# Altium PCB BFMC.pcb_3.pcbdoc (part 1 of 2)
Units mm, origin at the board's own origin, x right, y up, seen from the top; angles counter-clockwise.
Board outline 133.24 x 103.12 mm, 2 copper layers (Top Layer, Bottom Layer); 130 components, 62 nets, 361 pads, 103 vias.
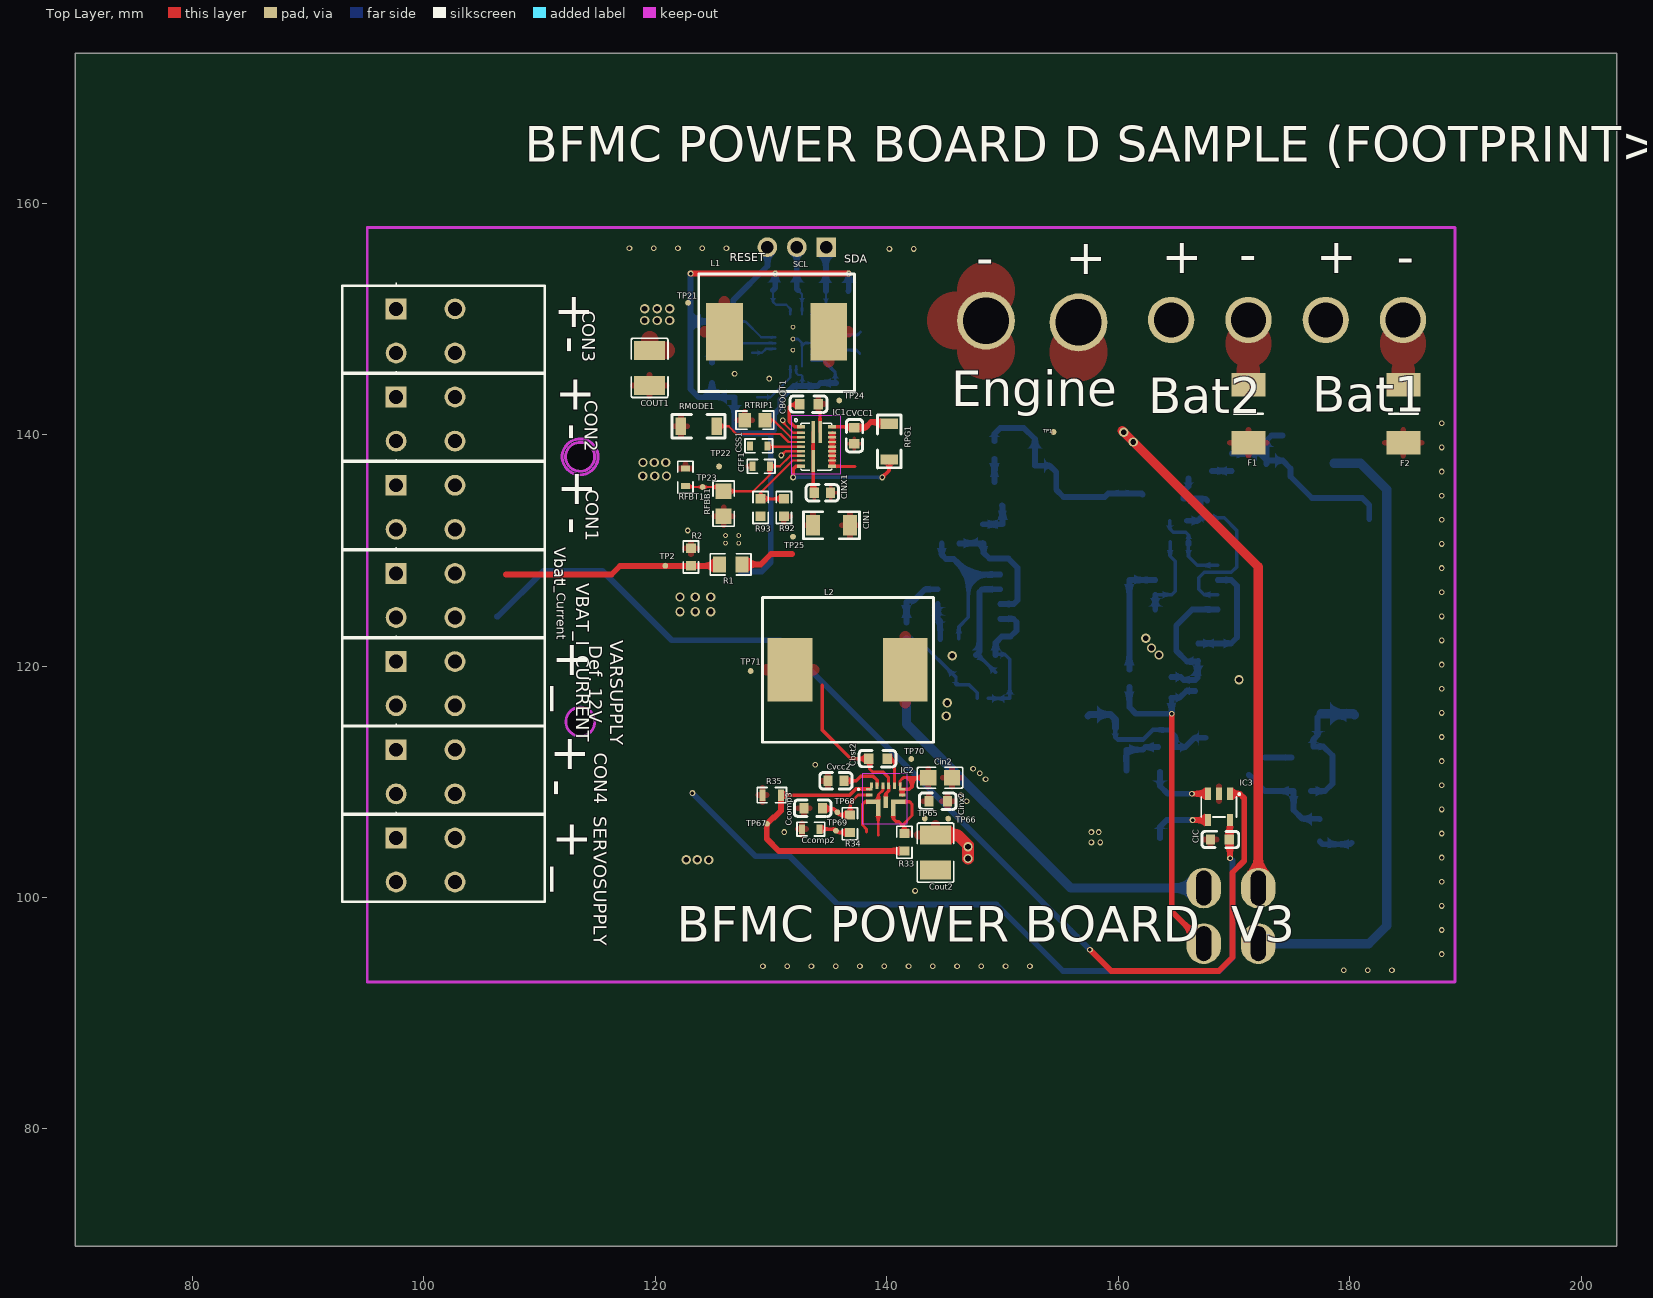
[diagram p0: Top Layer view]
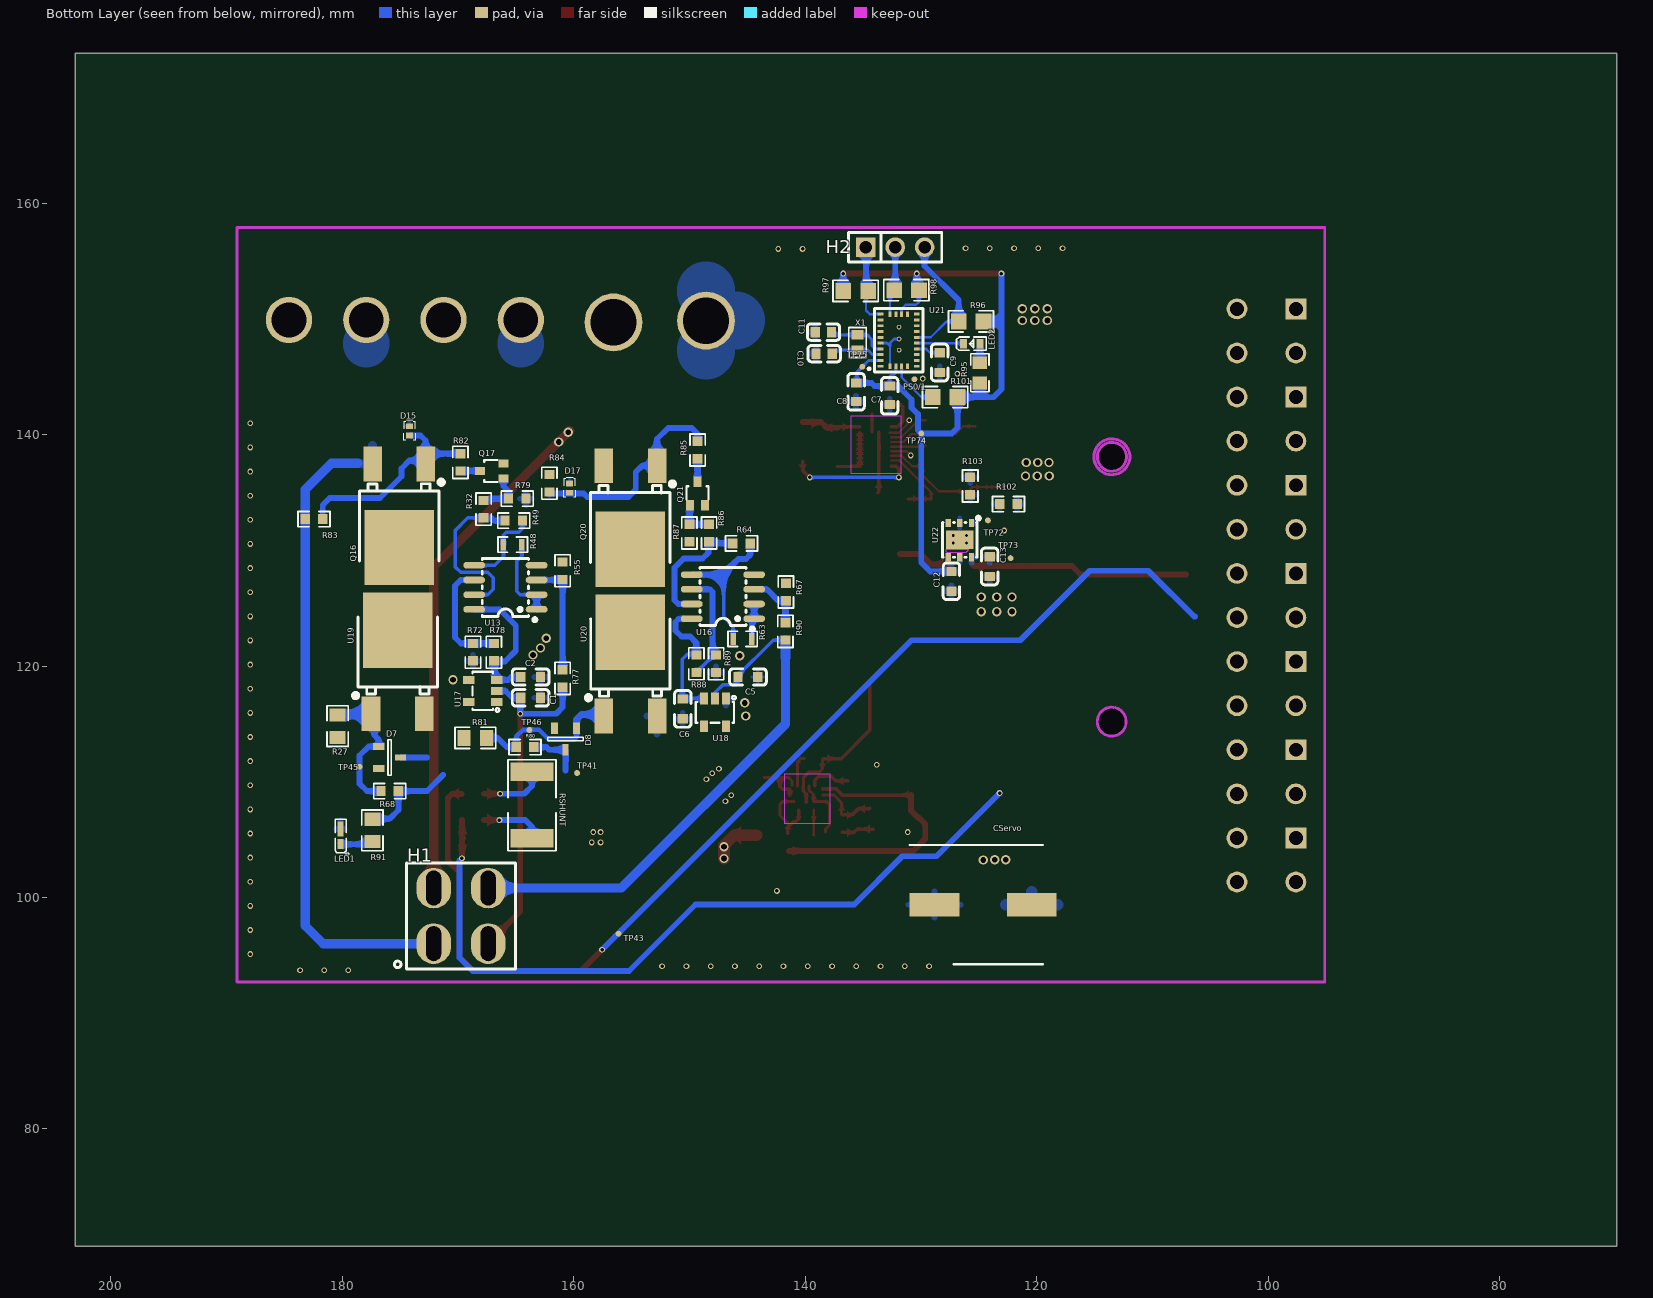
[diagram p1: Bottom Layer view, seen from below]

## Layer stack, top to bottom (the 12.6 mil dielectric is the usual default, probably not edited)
Top Layer: signal copper (thickness not stored)
Dielectric: dielectric 0.32, FR-4, Dk 4.8
Bottom Layer: signal copper (thickness not stored)

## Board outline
203.09,69.85 69.85,69.85 69.85,172.973 203.09,172.973
cut-out: 114.745,138.083 ccw(c113.495,138.083) 112.245,138.083 ccw(c113.495,138.083)
cut-out: 114.762,115.196 ccw(c113.512,115.196) 112.262,115.196 ccw(c113.512,115.196)

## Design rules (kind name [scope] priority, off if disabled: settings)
Clearance copperThickness1oz [All] p1: gap=0.178 ignorepadtopadclearanceinfootprint=FALSE except(0.102: Track-Track; 0.152: Track-SMDPad SMDPad-SMDPad Track-THPad SMDPad-THPad THPad-THPad Track-Via SMDPad-Via THPad-Via Via-Via Track-Fill SMDPad-Fill THPad-Fill Via-Fill Fill-Fill SMDPad-Region THPad-Region Via-Region Fill-Region Region-Region Track-Poly SMDPad-Poly THPad-Poly Via-Poly Fill-Poly Poly-Poly Track-Text SMDPad-Text THPad-Text Via-Text Fill-Text Region-Text Poly-Text Text-Text Track-Hole SMDPad-Hole THPad-Hole Via-Hole Fill-Hole Region-Hole Poly-Hole Text-Hole; 0.3: Track-Region Region-Poly Track-Sheet SMDPad-Sheet THPad-Sheet Via-Sheet Fill-Sheet Region-Sheet Poly-Sheet Text-Sheet Sheet-Hole)
Clearance copperThickness2oz [All] p1: gap=0.178 ignorepadtopadclearanceinfootprint=FALSE except(0.152: Track-SMDPad SMDPad-SMDPad Track-THPad SMDPad-THPad THPad-THPad Track-Via SMDPad-Via THPad-Via Via-Via Track-Fill SMDPad-Fill THPad-Fill Via-Fill Fill-Fill SMDPad-Region THPad-Region Via-Region Fill-Region Region-Region Track-Poly SMDPad-Poly THPad-Poly Via-Poly Fill-Poly Poly-Poly Track-Text SMDPad-Text THPad-Text Via-Text Fill-Text Region-Text Poly-Text Text-Text Track-Hole SMDPad-Hole THPad-Hole Via-Hole Fill-Hole Region-Hole Poly-Hole Text-Hole; 0.203: Track-Track; 0.3: Track-Region Region-Poly Track-Sheet SMDPad-Sheet THPad-Sheet Via-Sheet Fill-Sheet Region-Sheet Poly-Sheet Text-Sheet Sheet-Hole)
Clearance Supply-GND [All] p1: gap=0.178 ignorepadtopadclearanceinfootprint=FALSE except(0.5: Track-Track Track-SMDPad SMDPad-SMDPad Track-THPad SMDPad-THPad THPad-THPad Track-Via SMDPad-Via THPad-Via Via-Via Track-Fill SMDPad-Fill THPad-Fill Via-Fill Fill-Fill Track-Region SMDPad-Region THPad-Region Via-Region Fill-Region Region-Region Track-Poly SMDPad-Poly THPad-Poly Via-Poly Fill-Poly Region-Poly Poly-Poly Track-Text SMDPad-Text THPad-Text Via-Text Fill-Text Region-Text Poly-Text Text-Text Track-Sheet SMDPad-Sheet THPad-Sheet Via-Sheet Fill-Sheet Region-Sheet Poly-Sheet Text-Sheet Track-Hole SMDPad-Hole THPad-Hole Via-Hole Fill-Hole Region-Hole Poly-Hole Text-Hole Sheet-Hole)
DiffPairsRouting differentialPair [All] p1: maxuncoupledlength=10 maxlimit=5.9843 mostfreqgap=5.9843 toplayer_minwidth=5 toplayer_prefwidth=10 toplayer_maxwidth=100 bottomlayer_minwidth=5 bottomlayer_prefwidth=10 bottomlayer_maxwidth=100
PasteMaskExpansion pasteMaskExpansion [All] p1:
PlaneConnect innerPlane [All] p1: planeconnectstyle=Relief reliefexpansion=0.508 reliefentries=4 reliefconductorwidth=0.254 reliefairgap=0.254
PolygonConnect copperRegion [All] p1: connectstyle=Direct reliefentries=4 reliefconductorwidth=10 polygonreliefangle="90 Angle" airgapwidth=10
PolygonConnect copperRegion1 [All] p1: connectstyle=Relief reliefentries=4 reliefconductorwidth=10 polygonreliefangle="90 Angle" airgapwidth=10
PolygonConnect copperRegion2 [All] p1: connectstyle=Relief reliefentries=4 reliefconductorwidth=10 polygonreliefangle="90 Angle" airgapwidth=10
RoutingVias viaSize [All] p1: viastyle="Through Hole" holewidth=12.0078 minholewidth=11.811 maxholewidth=248.0314 width=24.0158 minwidth=19.685 maxwidth=393.7008
SolderMaskExpansion solderMaskExpansion [All] p1: useseparateexpansions=TRUE expansion=2.0079 expansionbottom=2.0079
Width copperThickness1oz [All] p1: maxlimit=100 minlimit=5 preferedwidth=10
Width copperThickness2oz [All] p1: maxlimit=100 minlimit=8 preferedwidth=10

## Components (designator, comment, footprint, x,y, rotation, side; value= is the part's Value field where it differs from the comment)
C1 "CAP_0201" C9 163.776,117.255 r180 bottom
C2 "CAP_0201" C9 163.776,119.055 r180 bottom
C5 "CAP_0201" C9 144.996,119.055 r180 bottom
C6 "CAP_0201" C9 150.576,116.355 r270 bottom
C7 "CAP_0201" Cbst2 132.696,143.295 r90 bottom
C8 "CAP_0201" Cbst2 135.6,143.76 r270 bottom
C9 "CAP_0201" C9 128.376,146.175 r90 bottom
C10 "CAP_0201" C0603 138.36,147 r0 bottom
C11 "CAP_0201" C0603 138.42,148.86 r0 bottom
C12 "CAP_0201" C9 127.356,127.275 r90 bottom
C13 "CAP_0201" C9 124.056,128.549 r90 bottom
CBOOT1 "EMK105 B7104KVHF" Cbst2 133.176,142.635 r0 top
Cbst2 "CAP_0201" Cbst2 139.139,112.005 r0 top
Ccomp2 "CAP_0201" "0603 0.5x0.8" 133.424,105.909 r0 top
Ccomp3 "CAP_0201" Cbst2 133.536,107.715 r0 top
CFF1 "C1005C0G1H220J" "0603 0.5x0.8" 129.138,137.264 r0 top
CIC "C2012X7S1C106K" Cbst2 168.876,105.015 r180 top
CIN1 "GCJ31CC71E106K" "Cin1 Aditome" 135.322,132.167 r0 top
Cin2 "CAP_0201" c0805 144.6,110.354 r180 top
CINX1 "GCM188C71A225K" C0603 134.433,134.961 r0 top
Cinx2 "CAP_0201" Cbst2 144.346,108.322 r0 top
CON1 "switch" "new connector" 100.14,133.721 r270 top
CON2 "switch" "new connector" 100.14,141.341 r270 top
CON3 "switch" "new connector" 100.14,148.961 r270 top
CON4 "switch" "new connector" 100.14,110.861 r270 top
COUT1 "EMK325ABJ107MM-T" C1210 119.5,145.76 r270 top
Cout2 "CAP_0201" C1210 144.207,103.879 r90 top
CServo "GCM188C71A225K" CAPAE1030X1050N 124.613,99.382 r180 bottom
CSS1 "C1608X7R1H154K" "0603 0.5x0.8" 128.933,139.017 r180 top
CVCC1 "GCM188C71A225K" C0603 137.2,139.9 r270 top
Cvcc2 "CAP_0201" C0603 135.607,110.079 r0 top
D7 "SZBZX84C18ET1G" SZBZX84C18ET1G 175.9,112.1 r270 bottom
D8 "SZBZX84C18ET1G" SZBZX84C18ET1G 160.7,113.7 r0 bottom
D15 "PZU6.8B2L,315" DFN1006-2L-RD 174.189,140.325 r270 bottom
D17 "PZU6.8B2L,315" DFN1006-2L-RD 160.346,135.372 r270 bottom
F1 "0451015.MRL" FUSC6127X294N 171.24,141.796 r270 top
F2 "0451015.MRL" FUSC6127X294N 184.628,141.796 r270 top
H1 "switch" M2021BB1W01 169.744,98.415 r0 bottom
H2 "HDR-M_2.54_1x3P" HDR-TH_3P-P2.54-V-M 132.216,156.195 r180 bottom
IC1 "TPS548A28RWWR" TPS548B28RWWR 133.925,138.963 r0 top
IC2 "TPS61288RQQR" TPS61288RQQR 139.907,108.479 r0 top
IC3 "INA180A2QDBVRQ1" ina180a2qdbvrq1 168.696,107.835 r180 top
L1 "IHLP4040DZERR47M11" IHLP4040DZERR47M11 130.476,148.815 r0 top
L2 "L_0402" "DR127-3R3-R (L2)" 136.607,119.692 r0 top
LED1 "19-213/Y2C-CQ2R2L/3T(CY)" LEDGREEN 180.156,105.375 r90 bottom
LED2 "TLMS1100-GS08" "LED2 RED" 125.676,147.855 r180 bottom
PS0/1 "Test-Point" Test-Point-0.5mm 130.56,144.78 r180 bottom
Q16 "IPD50P04P4-13" pg-to252-3_l6.3-w6.5-p4.57-ls10.0-br-cw 175.078,133.848 r90 bottom
Q17 "BC846W" SOT-323-3_L2.2-W1.3-P1.30-LS2.2-BR 167.08,136.86 r180 bottom
Q20 "IPD50P04P4-13" pg-to252-3_l6.3-w6.5-p4.57-ls10.0-br-cw 155.1,133.7 r90 bottom
Q21 "BC846W" SOT-323-3_L2.2-W1.3-P1.30-LS2.2-BR 149.3,134.9 r270 bottom
R1 "MCR03..PFX1051" R0805_NEW 126.504,128.785 r0 top
R2 "MCR03...PFX7680" R0603 123.075,129.42 r90 top
R27 "MCR03..PFX1002" R0805_NEW 180.4,114.8 r270 bottom
R32 "MCR03..PFX1002" R0603 167.78,133.56 r90 bottom
R33 "MCR03..PFX1002" R0603 141.507,104.779 r90 top
R34 "MCR03..PFX1002" R0603 136.807,106.379 r90 top
R35 "MCR03..PFX1002" R35 130.056,108.855 r180 top
R48 "Res_0603" R35 165.28,130.5 r0 bottom
R49 "Res_0603" R0603 165.18,132.56 r0 bottom
R55 "Res_0603" R0603 160.956,128.235 r270 bottom
R63 "Res_0603" R35 145.42,122.34 r0 bottom
R64 "Res_0603" R0603 145.5,130.6 r0 bottom
R67 "Res_0603" R0603 141.673,126.4 r270 bottom
R68 "Res_0603" R0603 175.9,109.2 r180 bottom
R72 "Res_0603" R0603 168.7,121.2 r270 bottom
R77 "Res_0603" R0603 160.956,118.935 r270 bottom
R78 "Res_0603" R0603 166.9,121.2 r270 bottom
R79 "Res_0603" R0603 164.88,134.46 r0 bottom
R80 "Res_0603" R0603 164.2,113 r180 bottom
R81 "MCR03..PFX1002" R0805_NEW 168.5,113.8 r0 bottom
R82 "Res_0603" R0603 169.797,137.602 r90 bottom
R83 "MCR03..PFX1002" R0603 182.444,132.705 r0 bottom
R84 "MCR03..PFX1002" R0603 162.1,135.8 r90 bottom
R85 "Res_0603" R0603 149.297,138.674 r90 bottom
R86 "MCR03..PFX1002" R0603 148.3,131.5 r270 bottom
R87 "Res_0603" R0603 150,131.5 r90 bottom
R88 "Res_0603" R0603 149.4,120.2 r270 bottom
R89 "Res_0603" R0603 147.7,120.2 r270 bottom
R90 "Res_0603" R0603 141.7,123 r90 bottom
R91 "Res_0603" R0805_NEW 177.4,105.8 r90 bottom
R92 "Res_0603" R0603 131.1,133.7 r270 top
R93 "Res_0603" R0603 129.1,133.7 r90 top
R95 "Res_0201" Rtrip 124.896,145.215 r90 bottom
R96 "Res_0201" "0805 dany2" 125.736,149.775 r180 bottom
R97 "Res_0201" "0805 dany2" 135.696,152.415 r180 bottom
R98 "Res_0201" "0805 dany2" 131.316,152.475 r180 bottom
R101 "Res_0201" "0805 dany2" 127.836,143.235 r0 bottom
R102 "Res_0201" R0603 122.436,133.995 r0 bottom
R103 "Res_0201" R0603 125.736,135.555 r90 bottom
RFBB1 "SMM0204 50 10K 1 %" "0805 dany2" 125.9,134.1 r270 top
RFBT1 "SMM0204 50 73K2 1 %" "0603 0.5x0.8" 122.6,136.32 r270 top
RMODE1 "SMM0204 50 30K1 1 %" "1206R aditome" 123.756,140.715 r180 top
RPG1 "SMM0204 50 30K1 1 %" "1206R aditome" 140.2,139.4 r90 top
RSHUNT "WSLP25122L500FEA" "WSLP25122L000FEA BUN" 163.6,108 r270 bottom
RTRIP1 "SMM0204 50 7K32 1 %" Rtrip 128.722,141.249 r180 top
SERVOSUPPLY "switch" "new connector" 100.14,103.241 r270 top
TP1 "Test-Point" Test-Point-0.5mm 154.405,140.222 r180 top
TP2 "Test-Point" Test-Point-0.5mm 120.856,128.662 r0 top
TP21 "Test-Point" Test-Point-0.5mm 122.824,151.384 r0 top
TP22 "Test-Point" Test-Point-0.5mm 125.504,137.247 r0 top
TP23 "Test-Point" Test-Point-0.5mm 124.083,135.469 r90 top
TP24 "Test-Point" Test-Point-0.5mm 135.887,142.946 r270 top
TP25 "Test-Point" Test-Point-0.5mm 131.887,131.181 r0 top
TP41 "Test-Point" Test-Point-0.5mm 159.708,110.758 r180 bottom
TP43 "Test-Point" Test-Point-0.5mm 156.126,96.876 r180 bottom
TP45 "Test-Point" Test-Point-0.5mm 178.5,111.3 r180 bottom
TP46 "Test-Point" Test-Point-0.5mm 163.827,114.474 r180 bottom
TP65 "Test-Point" Test-Point-0.5mm 143.275,106.819 r0 top
TP66 "Test-Point" Test-Point-0.5mm 145.298,106.817 r270 top
TP67 "Test-Point" Test-Point-0.5mm 129.637,106.37 r0 top
TP68 "Test-Point" Test-Point-0.5mm 135.722,107.37 r0 top
TP69 "Test-Point" Test-Point-0.5mm 135.6,105.768 r0 top
TP70 "Test-Point" Test-Point-0.5mm 142.107,111.979 r270 top
TP71 "Test-Point" Test-Point-0.5mm 128.23,119.571 r0 top
TP72 "Test-Point" Test-Point-0.5mm 124.207,132.587 r180 bottom
TP73 "Test-Point" Test-Point-0.5mm 122.247,129.327 r180 bottom
TP74 "Test-Point" Test-Point-0.5mm 129.96,140.1 r180 bottom
TP75 "Test-Point" Test-Point-0.5mm 135.06,145.86 r180 bottom
U13 "LT1490IS8#PBF" SO-8_L4.9-W3.9-P1.27-LS5.9-BL 165.9,126.8 r90 bottom
U16 "LT1490IS8#PBF" SO-8_L4.9-W3.9-P1.27-LS5.9-BL 147.1,126 r90 bottom
U17 "NCP715SN50T1G" TSOP-5_L3.0-W1.5-P0.95-BL 167.856,117.855 r90 bottom
U18 "NCP715SN50T1G" TSOP-5_L3.0-W1.5-P0.95-BL 147.8,116 r0 bottom
U19 "DMPH3010LK3-13" pg-to252-3_l6.3-w6.5-p4.57-ls10.0-br-cw 175.214,119.487 r270 bottom
U20 "DMPH3010LK3-13" pg-to252-3_l6.3-w6.5-p4.57-ls10.0-br-cw 155.1,119.3 r270 bottom
U21 "BNO055" LGA-28_L5.2-W3.8-P0.50-BL 131.916,148.155 r180 bottom
U22 "NCP708MU330TAG" DFN-6_L3.0-W3.0-P0.95-LS3.1-BL-EP 126.636,130.875 r0 bottom
VARSUPPLY "switch" "new connector" 100.14,118.481 r270 top
VBAT_I_CURRENT "switch" "new connector" 100.14,126.101 r270 top
X1 "ABS05-32.768kHz-T" OSC-SMD_2P-L1.6-W1.0 135.48,147.96 r270 bottom

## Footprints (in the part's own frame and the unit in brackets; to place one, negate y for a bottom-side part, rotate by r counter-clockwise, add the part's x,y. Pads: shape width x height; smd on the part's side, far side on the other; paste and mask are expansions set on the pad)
"0603 0.5x0.8" [mm]
  rect 0.5x0.8 smd: 1(-0.753,0) 2(0.753,0)
  silkscreen extent -1.2,-0.59 1.2,0.59
"0805 dany2" [mm]
  rect 1.35x1.377 smd: 1(-1,0) 2(1.15,0)
  silkscreen extent -1.89,-0.92 2.02,0.92
"1206R aditome" [mm]
  rect 0.9x1.5 smd: 1(-1.55,0) 2(1.55,0)
  silkscreen extent -2.27,-1.02 2.31,1.02
C9 [mm]
  rect 0.8x0.9 smd: 1(-0.8,0) 2(0.9,0)
  silkscreen extent -1.53,-0.71 1.64,0.72
C0603 [mm]
  rect 0.8x0.9 smd: 1(-0.7,0) 2(0.7,0)
  silkscreen extent -1.41,-0.71 1.39,0.72
c0805 [mm]
  rect 1.41x1.35 smd: 1(-1.03,0) 2(1.03,0)
  silkscreen extent -1.96,-0.9 1.96,0.9
C1210 [mm]
  rect 1.635x2.7 smd: 1(-1.517,0) 2(1.517,0)
  silkscreen extent -2.56,-1.58 2.56,1.58
CAPAE1030X1050N [mm]
  rect 4.3x2.05 smd: 1(-4.2,0) 2(4.2,0)
  silkscreen extent -6.35,-5.15 5.15,5.15
Cbst2 [mm]
  rect 0.8x0.9 smd: 1(-0.7,0) 2(0.9,0)
  silkscreen extent -1.53,-0.71 1.64,0.72
"Cin1 Aditome" [mm]
  rect 1.2x1.8 smd: 1(-1.7,0) 2(1.5,0)
  silkscreen extent -2.54,-1.17 2.33,1.17
DFN1006-2L-RD [mm]
  rect 0.5x0.6 smd: 1(-0.4,0) 2(0.4,0)
  silkscreen extent -0.9,-0.5 0.8,0.5
DFN-6_L3.0-W3.0-P0.95-LS3.1-BL-EP [mm]
  rect 0.45x0.701 smd: 1(-1.001,-1.476) 2(0,-1.476) 3(1.001,-1.476) 4(1.001,1.476) 5(0,1.476) 6(-1.001,1.476)
  rect 2.4x1.6 smd: 7(0,-0.025)
  silkscreen extent -1.75,-2.05 1.5,1.47
"DR127-3R3-R (L2)" [mm]
  rect 3.85x5.5 smd: 1(-4.975,0) 2(4.975,0)
  silkscreen extent -7.37,-6.28 7.42,6.22
FUSC6127X294N [mm]
  rect 2.02x2.95 smd: 1(-2.5,0) 2(2.5,0)
  silkscreen extent 0,-1.24 0,1.24
HDR-TH_3P-P2.54-V-M [mm]
  rect 1.7x1.7 hole 1.1: 1(-2.54,0)
  round 1.7 hole 1.1: 2(0,0) 3(2.54,0)
  silkscreen extent -4.02,-1.27 4.02,1.27
IHLP4040DZERR47M11 [mil]
  rect 125x195 smd: 1(-177.5,2.5) 2(177.5,2.5)
  silkscreen extent -265,-200 265,200
ina180a2qdbvrq1 [mm]
  rect 0.532x1.07 smd: 1(-0.95,-1.135) 2(0,-1.135) 3(0.95,-1.135) 4(0.95,1.135) 5(-0.95,1.135)
  silkscreen extent -1.9,-1.25 1.53,0.88
"LED2 RED" [mm]
  rect 0.6x0.8 smd: 1(-0.65,-0.003) 2(0.8,0.003)
  silkscreen extent -1.25,-0.57 1.32,0.58
LEDGREEN [mm]
  rect 1.3x0.5 smd: 1(0.55,0)
  rect 0.87x0.5 smd: 2(-0.765,0)
  silkscreen extent -1.74,-0.72 1.38,0.46
LGA-28_L5.2-W3.8-P0.50-BL [mm]
  rect 0.5x0.25 smd: 1(-1.563,-2.25) 6(1.563,-2.25) 7(1.563,-1.75) 8(1.563,-1.25) 9(1.563,-0.75) 10(1.563,-0.25) 11(1.563,0.25) 12(1.563,0.75) 13(1.563,1.25) 14(1.563,1.75) 15(1.563,2.25) 20(-1.563,2.25) 21(-1.563,1.75) 22(-1.563,1.25) 23(-1.563,0.75) 24(-1.563,0.25) 25(-1.563,-0.25) 26(-1.563,-0.75) 27(-1.563,-1.25) 28(-1.563,-1.75)
  rect 0.25x0.5 smd: 2(-0.75,-2.25) 3(-0.25,-2.25) 4(0.25,-2.25) 5(0.75,-2.25) 16(0.75,2.25) 17(0.25,2.25) 18(-0.25,2.25) 19(-0.75,2.25)
  silkscreen extent -2.66,-2.75 2.08,2.75
M2021BB1W01 [mm]
  oval 3x3.5 hole 1.3 slot 3 at 90 deg: 1(-2.35,-2.4) 2(2.35,-2.4) 3(-2.35,2.4) 4(2.35,2.4)
  silkscreen extent -4.7,-4.57 5.74,4.57
"new connector" [mm]
  rect 1.8x1.8 hole 1.2: 1(-1.905,-2.54)
  round 1.8 hole 1.2: 2(-1.905,2.54) 3(1.905,-2.54) 4(1.905,2.54)
  silkscreen extent -4.11,-7.19 3.61,10.31
OSC-SMD_2P-L1.6-W1.0 [mm]
  rect 0.8x1.06 smd: 1(-0.66,0) 2(0.66,0)
  silkscreen extent -1.29,-0.76 1.29,0.76
pg-to252-3_l6.3-w6.5-p4.57-ls10.0-br-cw [mm]
  rect 3x1.6 smd: 1(3.614,-2.299) 3(3.614,2.299)
  rect 6.5x6 smd: 2(-3.614,0.001)
  silkscreen extent -4.76,-3.83 2.24,3.43
R35 [mm]
  rect 0.5x1 smd: 1(-0.8,0) 2(0.8,0)
  silkscreen extent -1.28,-0.66 1.25,0.66
R0603 [mm]
  rect 0.806x0.864 smd: 1(-0.753,0) 2(0.753,0)
  silkscreen extent -1.39,-0.66 1.39,0.66
R0805_NEW [mm]
  rect 1.133x1.377 smd: 1(-0.966,0) 2(0.966,0)
  silkscreen extent -1.76,-0.92 1.76,0.92
Rtrip [mm]
  rect 1.1x1.25 smd: 1(-0.753,0) 2(0.997,0)
  silkscreen extent -1.51,-0.79 1.77,0.79
SO-8_L4.9-W3.9-P1.27-LS5.9-BL [mm]
  oval 0.574x1.888 smd: 1(-1.905,-2.699) 2(-0.635,-2.699) 3(0.635,-2.699) 4(1.905,-2.699) 5(1.905,2.699) 6(0.635,2.699) 7(-0.635,2.699) 8(-1.905,2.699)
  silkscreen extent -2.94,-2.69 2.5,2
SOT-323-3_L2.2-W1.3-P1.30-LS2.2-BR [mm]
  rect 0.9x0.7 smd: 1(1.016,-0.66) 2(1.016,0.66) 3(-1.016,0)
  silkscreen extent -0.65,-0.95 0.48,0.95
SZBZX84C18ET1G [mm]
  rect 0.61x0.975 smd: 1(-0.95,-0.937) 2(0.95,-0.937)
  rect 0.523x0.975 smd: 3(0,0.937)
  silkscreen extent -1.54,-0.14 1.54,0.14
Test-Point-0.5mm [mm]
  round 0.5 smd: 1(0,0)
TPS548B28RWWR [mm]
  rect 0.7x0.3 smd: 1(-1.35,1.7) 9(-1.35,-1.7) 11(1.35,-1.7) 19(1.35,1.7)
  rect 0.7x0.2 smd: 2(-1.35,1.2) 3(-1.35,0.8) 4(-1.35,0.4) 5(-1.35,0) 6(-1.35,-0.4) 7(-1.35,-0.8) 8(-1.35,-1.2) 12(1.35,-1.2) 13(1.35,-0.8) 14(1.35,-0.4) 15(1.35,0) 16(1.35,0.4) 17(1.35,0.8) 18(1.35,1.2)
  rect 0.3x1.9 smd: 10(-0.3,-1.25) 20(0.3,1.25) 21(-0.3,1.25)
  silkscreen extent -1.9,-2.03 1.32,2.41
TPS61288RQQR [mm]
  rect 0.575x0.25 smd: 1(-1.413,0.875) 7(1.413,0.875)
  rect 0.55x0.25 smd: 2(-1.425,0.375) 6(1.425,0.375)
  rect 1.25x0.4 smd: 3(-1.075,-0.2) 5(1.075,-0.2)
  rect 0.4x1 smd: 4(0,-0.25)
  rect 0.25x0.55 smd: 8(0.75,1.175) 9(0.25,1.175) 10(-0.25,1.175) 11(-0.75,1.175)
  rect 0.225x0.45 smd: 12(-1.237,1.225) 15(1.237,1.225)
  rect 0.4x1.05 smd: 13(-0.65,-0.925) 14(0.65,-0.925)
  silkscreen extent -2.4,0.83 -2.3,0.92
TSOP-5_L3.0-W1.5-P0.95-BL [mm]
  rect 0.7x1 smd: 1(-0.95,-1.2) 2(0,-1.2) 3(0.95,-1.2) 4(0.95,1.2) 5(-0.95,1.2)
  silkscreen extent -1.8,-1.42 1.65,0.89
"WSLP25122L000FEA BUN" [mm]
  rect 1.6x3.68 smd: 1(-2.875,0) 2(2.875,0)
  silkscreen extent -3.91,-2.07 3.96,2.07

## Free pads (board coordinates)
  round 0.4 hole 0.25: 1(126.06,130.62) 1(126.06,131.28) 1(127.2,130.62) 1(127.2,131.28) 1(131.89,149.285) 2(131.88,148.26) 4(131.88,147.3)
  round 0.5 hole 0.3: 1(126.84,145.26) 1(129.84,144.84)
  round 5 hole 4: 22(148.563,149.85) 22(156.563,149.7)
  round 4 hole 3: 22(164.563,149.91) 22(171.243,149.91) 22(177.923,149.91) 22(184.603,149.91)

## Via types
v1: diameter 0.5, hole 0.3, Top Layer to Bottom Layer, 71 vias
v2: diameter 0.8, hole 0.5, Top Layer to Bottom Layer, 32 vias

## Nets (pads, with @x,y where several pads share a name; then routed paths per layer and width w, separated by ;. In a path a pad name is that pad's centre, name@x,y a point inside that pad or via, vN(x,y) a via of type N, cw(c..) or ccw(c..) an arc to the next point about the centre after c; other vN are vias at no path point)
$1N1788: D8.1 R80.1 R81.1 TP46.1 U20.1 | length 13.8
  Bottom Layer w0.4: D8.1@159.75,114.637 159.75,113.841 159.936,113.655 162.156,113.655 162.998,114.497 163.803,114.497 TP46.1@163.827,114.474 164.397,114.474 164.953,113.918 R80.1@164.953,113
  Bottom Layer w0.5: R80.1@164.953,113 165.787,113 166.587,113.8 R81.1@167.533,113.8
  Bottom Layer w0.6: U20.1@157.399,115.686 157.528,115.815 159.336,115.815 159.75,115.401 D8.1@159.75,114.637
$1N1798: D7.1 R27.1 R68.1 TP45.1 U19.1 | length 12.6
  Bottom Layer w0.5: R68.1@176.653,109.2 177.862,109.2 178.5,109.838 TP45.1@178.5,111.3 178.5,112.265 177.715,113.05 D7.1@176.837,113.05 176.837,113.636 177.214,114.013 177.214,115.573 U19.1@177.514,115.873
  Bottom Layer w0.8: U19.1@177.514,115.873 180.293,115.873 R27.1@180.4,115.766
$1N2164: Q16.2 U19.2
$1N2337: D15.2 Q16.1 R82.2 R83.1 | length 19.3
  Bottom Layer w0.5: R82.2@169.797,138.355 172.244,138.355 172.778,137.821 Q16.1@172.778,137.462 172.8,137.484 Q16.1@172.8,137.76 ; D15.2@174.189,139.925 173.246,139.925 172.8,139.479 Q16.1@172.8,137.76 ; R83.1@181.69,132.705 181.69,133.909 181.08,134.52 176.734,134.52 174.88,136.374 174.88,137.081 174.201,137.76 Q16.1@172.8,137.76
$1N2412: Q17.3 R82.1 | length 1.7
  Bottom Layer w0.5: Q17.3@168.096,136.86 169.785,136.86 R82.1@169.797,136.849
$1N2516: Q17.1 R32.2 R79.2 | length 4
  Bottom Layer w0.5: Q17.1@166.064,136.2 166.064,135.544 165.633,135.113 R79.2@165.633,134.46 167.533,134.46 R32.2@167.68,134.313
$1N20674: R55.2 R77.1 U13.3 | length 10
  Bottom Layer w0.5: R77.1@160.956,119.688 160.956,127.422 160.969,127.435 U13.3@163.201,127.435
$1N20931: R48.1 U13.1 U13.2 | length 7.6
  Bottom Layer w0.3: U13.2@163.201,126.165 164.618,126.165 164.918,126.465 164.918,129.065 164.48,129.503 R48.1@164.48,130.74
  Bottom Layer w0.5: U13.1@163.201,124.895 U13.2@163.201,126.165
$1N20946: R48.2 R49.1 U13.5 | length 7.3
  Bottom Layer w0.3: R49.1@164.426,132.56 164.426,131.893 164.74,131.58 165.82,131.58 166.06,131.34 R48.2@166.06,130.72 ; R48.2@166.08,130.5 166.06,130.52 166.06,129.48 166.835,128.705 U13.5@168.599,128.705
  Bottom Layer w0.5: R48.2@166.06,130.52 R48.2@166.06,130.72
$1N20962: R32.1 R49.2 U13.7 | length 14.5
  Bottom Layer w0.3: R32.1@167.78,132.807 169.153,132.807 170.252,131.708 170.252,128.591 169.761,128.1 167.419,128.1 166.95,127.63 166.95,126.624 167.409,126.165 U13.7@168.599,126.165
  Bottom Layer w0.5: R49.2@165.933,132.56 166.88,132.56 167.126,132.807 R32.1@167.78,132.807
$1N21052: R72.1 R78.1 U13.6 | length 9.9
  Bottom Layer w0.5: R78.1@166.9,121.953 R72.1@168.7,121.953 169.734,121.953 170.256,122.475 170.256,126.935 169.756,127.435 U13.6@168.599,127.435
$1N27791: Q20.2 U20.2
$1N27792: D17.2 Q20.1 R84.1 R85.2 | length 18.5
  Bottom Layer w0.5: R85.2@149.297,139.427 149.297,140.079 149.797,140.579 151.837,140.579 152.8,139.615 Q20.1@152.8,137.314 154.086,137.314 154.631,136.769 154.631,135.245 155.266,134.61 158.822,134.61 159.122,134.91 162.023,134.91 R84.1@162.1,134.834
$1N27793: Q21.3 R85.1 | length 2
  Bottom Layer w0.5: R85.1@149.297,137.921 149.3,137.918 Q21.3@149.3,135.916
$1N27799: Q21.1 R86.1 R87.2 | length 3.3
  Bottom Layer w0.5: R86.1@148.3,132.253 R87.2@150,132.253 150,133.844 Q21.1@149.96,133.884
$1N27802: R63.1 U16.1 U16.2 | length 3.1
  Bottom Layer w0.5: U16.2@144.401,125.365 U16.1@144.401,124.095 144.62,123.876 R63.1@144.62,122.34
$1N27807: R63.2 R64.1 U16.5 | length 12.6
  Bottom Layer w0.3: R63.2@146.22,122.34 146.22,123.38 147.041,124.201 147.041,127.9 ; U16.5@149.794,127.9 U16.5@149.799,127.905
  Bottom Layer w0.5: R64.1@144.746,130.6 144.746,129.625 145.116,129.255 145.776,129.255 147.126,127.905 U16.5@149.799,127.905
$1N27811: R64.2 R86.2 U16.7 | length 11
  Bottom Layer w0.3: R86.2@148.153,130.6 R86.2@148.3,130.747
  Bottom Layer w0.5: R64.2@146.253,130.6 148.153,130.6 148.36,130.6 148.36,129.8 148.86,129.3 150.5,129.3 151.3,128.5 151.3,125.691 150.974,125.365 U16.7@149.799,125.365
$1N27822: R67.2 R90.2 U16.3 | length 4.9
  Bottom Layer w0.3: R67.2@141.7,125.547 R67.2@141.8,125.647
  Bottom Layer w0.5: R90.2@141.7,123.753 R67.2@141.7,125.547 ; R67.2@141.8,125.647 142.318,125.647 143.307,126.635 U16.3@144.401,126.635
$1N32332: R88.2 R89.1 U16.6 | length 9.8
  Bottom Layer w0.3: R89.1@147.7,120.953 147.893,120.953 R88.2@149.4,119.447
  Bottom Layer w0.5: R89.1@147.7,120.953 148,121.253 148,126.4 148.235,126.635 U16.6@149.799,126.635
$1N40141: LED1.2 R91.1 | length 2.9
  Bottom Layer w0.5: R91.1@177.4,104.834 177.638,104.595 180.021,104.595 LED1.2@180.156,104.73
$2N28: F1.1 pad.22@171.243,149.91
$2N30: F2.1 pad.22@184.603,149.91
$3N2936: Ccomp2.2 R34.1 TP69.1 | length 2.8
  Top Layer w0.3: Ccomp2.2@134.118,105.915 135.498,105.915 135.788,105.626 R34.1@136.807,105.626
$5N394: C9.2 U21.9 | length 2.1
  Bottom Layer w0.2: C9.2@128.376,147.075 129.216,147.075 129.546,147.405 U21.9@130.353,147.405
$5N959: LED2.2 R95.2 | length 1.7
  Bottom Layer w0.5: LED2.2@124.876,147.859 124.896,147.839 R95.2@124.896,146.212
$5N968: LED2.1 U21.10 | length 4
  Bottom Layer w0.2: LED2.1@126.356,147.852 126.409,147.905 U21.10@130.353,147.905
$5N2144: R101.2 U21.4 | length 4.5
  Bottom Layer w0.2: R101.2@128.802,143.235 129.936,143.235 131.666,144.965 U21.4@131.666,145.905
+3V3: C7.2 C8.1 C12.2 R95.1 R96.2 R97.1 R98.2 R101.1 TP74.1 TP75.1 U21.3 U21.17 U21.28 U22.4 U22.5 | length 71
  Top Layer w0.5: v1(123.036,153.915) v1(130.356,153.915) v1(136.716,153.915)
  Bottom Layer w0.2: R98.2@130.166,152.475 130.166,151.465 130.416,151.215 131.316,151.215 131.666,150.865 U21.17@131.666,150.405 ; U21.3@132.166,145.905 132.166,145.325 132.336,145.155 132.576,145.155 132.696,145.035 C7.2@132.696,144.195
  Bottom Layer w0.254: U21.28@133.479,146.405 134.515,146.405 TP75.1@135.06,145.86 135.54,145.38 135.54,144.52 C8.1@135.6,144.46
  Bottom Layer w0.5: v1(123.036,153.915) 123.025,153.905 123.025,149.759 ; R96.2@124.586,149.775 123.042,149.775 123.025,149.759 ; R95.1@124.896,144.462 124.896,143.241 124.89,143.235 ; C12.2@127.356,128.175 129.195,128.175 129.96,128.94 TP74.1@129.96,140.1 ; R98.2@130.166,152.475 130.35,152.659 130.35,153.909 v1(130.356,153.915) ; C8.1@135.6,144.46 134.26,144.46 133.995,144.195 C7.2@132.696,144.195 131.955,144.195 130.8,143.04 130.8,142.32 130.26,141.78 130.26,140.4 TP74.1@129.96,140.1 ; R97.1@136.662,152.415 136.716,152.469 v1(136.716,153.915) ; 123.025,149.759 123.025,143.929 123.719,143.235 124.89,143.235 ; 124.89,143.235 R101.1@126.836,143.235 126.836,140.6 127.336,140.1 TP74.1@129.96,140.1
+5V: C13.2 CFF1.1 CIC.1 Cin2.2 Cinx2.1 CON1.1 CON1.2 CON2.1 CON2.2 CON3.1 CON3.2 CON4.1 CON4.2 COUT1.1 CServo.2 IC2.6 IC2.7 IC2.15 IC3.5 L1.1 L2.2 R102.1 RFBT1.1 SERVOSUPPLY.1 SERVOSUPPLY.2 TP21.1 TP22.1 TP70.1 TP73.1 U22.6 | length 70.6
  Top Layer w0.254: IC2.15@141.144,109.704 141.144,110.073 141.425,110.354 Cin2.2@143.57,110.354
  Top Layer w0.3: IC2.7@141.32,109.354 IC2.7@141.332,109.342 ; IC2.6@141.332,108.854 IC2.7@141.332,109.342 ; 142.171,110.285 142.177,110.279 142.177,109.592 141.927,109.342 IC2.7@141.332,109.342
  Top Layer w0.5: IC3.5@169.646,106.7 169.646,105.205 169.576,105.135 169.656,105.055 v1(169.656,103.395)
  Bottom Layer w0.5: v1(123.199,109.02) 128.659,103.56 131.605,103.56 135.757,99.408 149.466,99.408 155.215,93.66 168.72,93.66 169.86,94.8 169.86,103.191 v1(169.656,103.395)
  other v2: 122.659,103.26 123.616,103.26 124.613,103.246 122.119,124.704 123.452,124.704 124.786,124.704 122.119,125.974 123.452,125.974 124.786,125.974 118.913,136.428 119.941,136.428 120.968,136.428 118.931,137.582 119.91,137.582 120.89,137.582 119.071,149.85 120.15,149.85 121.23,149.85 119.071,150.866 120.15,150.866 121.23,150.866
+VCC2: C2.1 R78.2 U13.8 U17.3 | length 12.5
  Bottom Layer w0.5: C2.1@164.576,119.055 165.396,119.055 165.646,118.805 U17.3@166.656,118.805 166.839,118.988 R78.2@166.839,120.386 ; R78.2@166.9,120.447 R78.2@166.839,120.386 ; U13.8@168.599,124.895 166.395,124.895 165,123.5 165,121.32 165.934,120.386 R78.2@166.839,120.386
+VCC3: C6.1 R88.1 U16.8 U18.3 | length 12.3
  Bottom Layer w0.3: U18.3@148.75,117.2 150.618,117.2 150.618,120.588 150.186,121.021 149.467,121.021 R88.1@149.4,120.953
  Bottom Layer w0.5: R88.1@149.4,120.953 149.4,122.013 149.932,122.545 150.694,122.545 151.202,123.053 151.202,123.815 150.948,124.069 149.825,124.069 U16.8@149.799,124.095
ADC1: R1.1 R2.1 TP2.1 VBAT_I_CURRENT.1 VBAT_I_CURRENT.2 | length 18.8
  Top Layer w0.5: 107.08,127.92 116.2,127.92 116.935,128.655 R2.1@123.063,128.655 ; R2.1@123.075,128.667 R2.1@123.063,128.655 ; R1.1@125.537,128.785 125.407,128.655 R2.1@123.063,128.655
BOOT: CBOOT1.1 IC1.1 | length 3.4
  Top Layer w0.3: CBOOT1.1@132.416,142.635 132.356,142.575 131.736,142.575 131.556,142.395 131.556,141.135 132.028,140.663 IC1.1@132.575,140.663
BST: Cbst2.2 IC2.8 | length 2.8
  Top Layer w0.254: Cbst2.2@140.039,112.005 140.409,112.005 140.657,111.758 IC2.8@140.657,109.654
COMP: Ccomp3.2 IC2.2 R34.2 TP68.1 | length 5.6
  Top Layer w0.254: R34.2@136.807,107.132 136.851,107.176 136.851,108.194 137.511,108.854 IC2.2@138.482,108.854
  Top Layer w0.3: Ccomp3.2@134.436,107.715 134.472,107.679 135.407,107.679 135.953,107.132 R34.2@136.807,107.132
EN: IC1.8 R92.1 R93.2 | length 7.2
  Top Layer w0.2: R93.2@129.1,134.453 129.1,135 131.863,137.763 IC1.8@132.575,137.763
  Top Layer w0.254: R93.2@129.1,134.453 R92.1@131.1,134.453
EN3V3: R102.2 R103.1 TP72.1 U22.1
FB: CFF1.2 IC1.7 RFBB1.1 RFBT1.2 TP23.1 | length 11.9
  Top Layer w0.2: RFBT1.2@122.6,135.567 122.78,135.567 122.877,135.469 TP23.1@124.083,135.469 125.531,135.469 RFBB1.1@125.9,135.1 128.461,135.1 129.891,136.53 CFF1.2@129.891,137.264 130.745,137.264 131.644,138.163 IC1.7@132.575,138.163
FB_1: IC2.1 IC2.12 R33.1 R35.1 TP67.1 | length 24.4
  Top Layer w0.3: R35.1@130.856,108.855 136.783,108.855 137.307,109.379 138.469,109.379 IC2.1@138.494,109.354
  Top Layer w0.5: R35.1@130.856,108.855 130.856,107.505 130.277,106.925 130.192,106.925 TP67.1@129.637,106.37 129.614,106.347 129.614,105.071 130.66,104.026 R33.1@141.407,104.026
GND: 
GPIO6: H2.3 R96.1 U21.11 | length 11.8
  Bottom Layer w0.2: R96.1@126.736,149.775 127.776,149.775 129.146,148.405 U21.11@130.353,148.405
  Bottom Layer w0.5: R96.1@126.736,149.775 126.736,151.615 129.696,154.575 H2.3@129.696,155.455 ; H2.3@129.676,155.475 H2.3@129.696,155.455 ; H2.3@129.696,156.175 H2.3@129.696,155.455
ISHUNT: IC3.1 TP43.1 VBAT_I_CURRENT.3 VBAT_I_CURRENT.4 | length 95.6
  Top Layer w0.5: v1(157.552,95.494) 159.386,93.66 168.672,93.66 169.86,94.848 169.86,102.159 170.887,103.186 170.887,108.575 170.514,108.948 IC3.1@169.668,108.948
  Bottom Layer w0.3: TP43.1@156.126,96.876 TP43.1@156.169,96.876
  Bottom Layer w0.5: 106.323,124.277 106.377,124.277 110.345,128.245 115.402,128.245 121.422,122.225 130.82,122.225 156.169,96.876 v1(157.552,95.494)
MODE: IC1.4 RMODE1.1 | length 7.8
  Top Layer w0.2: RMODE1.1@125.306,140.715 126.336,140.715 126.996,140.055 130.8,140.055 131.493,139.363 IC1.4@132.575,139.363
OUT_BATT: CIN1.1 CINX1.1 IC1.10 IC1.21 IC3.4 pad.22@156.563,149.7 R1.2 R92.2 RSHUNT.2 TP1.1 TP25.1 | length 15.4
  Top Layer w0.3: IC1.21@133.625,140.213 IC1.10@133.625,137.713 133.625,135.069 CINX1.1@133.732,134.961
  Top Layer w0.5: R1.2@127.47,128.785 129.106,128.785 129.996,129.675 131.796,129.675 ; v1(166.416,106.695) 167.741,106.695 IC3.4@167.746,106.7
  Bottom Layer w0.5: RSHUNT.2@163.6,105.125 163.6,106.114 164.181,106.695 v1(166.416,106.695)
  other v1: 157.679,104.765 158.441,104.765 157.679,105.654 158.314,105.654
OUT_BATT1: D15.1 H1.4 pad.22@177.923,149.91 Q16.3 R83.2 | length 54.9
  Bottom Layer w0.8: H1.4@172.094,96.015 181.643,96.015 183.197,97.569 R83.2@183.197,132.705 183.197,135.263 180.929,137.531 178.634,137.531
OUT_BATT2: D17.1 H1.2 pad.22@164.563,149.91 Q20.3 R84.2 | length 44.4
  Top Layer w0.8: v2@160.346,140.325 v2(161.3,139.371) 172.094,128.577 H1.2@172.094,100.815
  other v2: 160.473,140.198
PGOOD: IC1.9 RPG1.1 | length 10.8
  Top Layer w0.3: v1@131.893,136.316 131.893,137.009 132.147,137.263 IC1.9@132.575,137.263 ; v1(139.6,136.3) 140.2,136.9 RPG1.1@140.2,137.7
  Bottom Layer w0.3: v1(131.9,136.3) v1(139.6,136.3)
SCK/SCL: H2.2 R98.1 U21.19 | length 6
  Bottom Layer w0.2: R98.1@132.316,152.475 132.666,152.125 U21.19@132.666,150.405
  Bottom Layer w0.5: H2.2@132.216,156.195 132.216,152.575 R98.1@132.316,152.475
SDI/SDA: H2.1 R97.2 U21.20 | length 6.9
  Bottom Layer w0.2: U21.20@133.479,150.405 134.406,150.405 134.736,150.735 134.736,152.409 R97.2@134.73,152.415
  Bottom Layer w0.5: R97.2@134.73,152.415 H2.1@134.73,155.449 ; H2.1@134.73,156.169 H2.1@134.73,155.449 ; H2.1@134.756,155.475 H2.1@134.73,155.449
SS_REFIN: CSS1.1 IC1.5 | length 3
  Top Layer w0.2: CSS1.1@129.633,139.077 129.746,138.963 IC1.5@132.575,138.963
SW: CBOOT1.2 IC1.20 L1.2 TP24.1 | length 1.6
  Top Layer w0.254: IC1.20@134.225,140.213 134.225,141.8
SW_1: Cbst2.1 IC2.4 IC2.9 L2.1 TP71.1 | length 14
  Top Layer w0.254: Cbst2.1@138.439,112.005 138.504,111.94 138.504,111.116 138.758,110.862 139.647,110.862 140.157,110.353 IC2.9@140.157,109.654
  Top Layer w0.3: 134.438,118.334 134.438,114.448 136.88,112.005 Cbst2.1@138.439,112.005 ; IC2.4@139.907,108.229 139.907,108.979 140.157,109.229 IC2.9@140.157,109.654
TRIP: IC1.3 RTRIP1.1 | length 3.6
  Top Layer w0.2: RTRIP1.1@129.564,141.23 129.583,141.249 130.207,141.249 131.693,139.763 IC1.3@132.575,139.763
UBATT: D7.3 D8.3 IC3.3 R68.2 R80.2 R91.2 RSHUNT.1 TP41.1 U19.3 U20.3 | length 21.3
  Top Layer w0.5: v1(166.356,108.975) 167.741,108.975 IC3.3@167.746,108.97
  Bottom Layer w0.5: 160.7,110.988 D8.3@160.7,112.763 162.12,112.763 162.358,113 R80.2@163.446,113 ; RSHUNT.1@163.6,110.875 163.6,109.639 164.263,108.975 v1(166.356,108.975) ; 171.268,110.607 172.675,109.2 R68.2@175.146,109.2 175.146,107.553 175.9,106.8 177.366,106.8 R91.2@177.4,106.766 ; 172.665,112.1 D7.3@174.962,112.1
VBATT1: C1.1 H1.3 R77.2 U17.2 | length 30.4
  Top Layer w0.5: v1(164.616,115.875) 164.616,98.793 H1.3@167.394,96.015
  Bottom Layer w0.5: R77.2@160.956,118.182 160.956,116.435 161.516,115.875 v1(164.616,115.875) 164.616,117.255 C1.1@164.576,117.255 165.283,117.255 165.883,117.855 U17.2@166.656,117.855
VBATT2: C5.1 H1.1 R90.1 U18.2 | length 47.7
  Bottom Layer w0.3: R90.1@141.7,122.247 142.753,122.247 145.974,119.026 145.974,118.4 146.4,118.4 147.1,118.4 147.8,117.7 U18.2@147.8,117.2
  Bottom Layer w0.8: R90.1@141.7,122.247 141.7,115 155.885,100.815 H1.1@167.394,100.815
VCC: CVCC1.1 IC1.19 RPG1.2 | length 5.2
  Top Layer w0.3: IC1.19@135.275,140.663 137.137,140.663 CVCC1.1@137.2,140.6
  Top Layer w0.5: CVCC1.1@137.2,140.6 138.143,140.6 138.631,141.088 140.188,141.088 RPG1.2@140.2,141.1
VCCBOOST: Cvcc2.2 IC2.11 | length 3.6
  Top Layer w0.3: Cvcc2.2@136.306,110.079 137.34,110.079 137.74,110.479 138.807,110.479 139.157,110.129 IC2.11@139.157,109.654
VOUT1: Cout2.2 IC2.5 IC2.14 R33.2 TP65.1 TP66.1 VARSUPPLY.1 VARSUPPLY.2 | length 10.3
  Top Layer w0.254: IC2.5@140.982,108.279 141.973,108.279 142.185,108.067 142.185,107.082 141.344,106.241
  Top Layer w0.3: IC2.14@140.557,107.554 140.557,106.797 140.811,106.543 141.042,106.543 141.344,106.241 141.507,106.078 R33.2@141.507,105.532
  Top Layer w1: Cout2.2@144.207,105.396 146.125,105.396 147.011,104.511 v2(147.011,104.384) v2(147.011,103.368)
XIN32: C10.1 U21.27 X1.2 | length 4.5
  Bottom Layer w0.254: U21.27@133.479,146.905 134.185,146.905 134.58,147.3 X1.2@135.48,147.3 137.36,147.3 C10.1@137.66,147
XOUT32: C11.1 U21.26 X1.1 | length 5.2
  Bottom Layer w0.254: U21.26@133.479,147.405 133.965,147.405 134.22,147.66 134.22,148.2 134.64,148.62 X1.1@135.48,148.62 137.48,148.62 C11.1@137.72,148.86
pads on no net: C1.2 C2.2 C5.2 C6.2 C7.1 C8.2 C9.1 C10.2 C11.2 C12.1 C13.1 Ccomp2.1 Ccomp3.1 CIC.2 CIN1.2 Cin2.1 CINX1.2 Cinx2.2 CON1.3 CON1.4 CON2.3 CON2.4 CON3.3 CON3.4 CON4.3 CON4.4 COUT1.2 Cout2.1 CServo.1 CSS1.2 CVCC1.2 Cvcc2.1 D7.2 D8.2 F1.2 F2.2 IC1.2 IC1.6 IC1.11 IC1.12 IC1.13 IC1.14 IC1.15 IC1.16 IC1.17 IC1.18 IC2.3 IC2.10 IC2.13 IC3.2 LED1.1 PS0/1.1 Q17.2 Q21.2 R2.2 R27.2 R35.2 R55.1 R67.1 R72.2 R79.1 R81.2 R87.1 R89.2 R93.1 R103.2 RFBB1.2 RMODE1.2 RTRIP1.2 SERVOSUPPLY.3 SERVOSUPPLY.4 U13.4 U16.4 U17.1 U17.4 U17.5 U18.1 U18.4 U18.5 U21.1 U21.2 U21.5 U21.6 U21.7 U21.8 U21.12 U21.13 U21.14 U21.15 U21.16 U21.18 U21.21 U21.22 U21.23 U21.24 U21.25 U22.2 U22.3 U22.7 VARSUPPLY.3 VARSUPPLY.4
copper on no net: | length 20.5
  Top Layer w0.2: v1(130.877,138.201) 131.239,138.563 132.575,138.563 ; v1@131.001,141.247 131.001,141.072 131.91,140.163 132.702,140.163
  Top Layer w0.254: 135.275,137.263 137.239,137.263 ; 138.248,105.654 138.248,105.908 137.898,106.257 137.898,108.067 138.11,108.279 138.832,108.279 139.279,108.279 139.279,108.9 139.657,109.277 139.657,109.654 ; 139.257,107.554 139.257,105.4 139.264,105.4
  Top Layer w0.3: 135.275,137.263 135.275,137.763 135.275,138.163 135.275,138.563 135.275,138.963 135.275,139.363 135.275,139.763 135.275,140.163
  Bottom Layer w0.2: 132.666,145.905 132.666,147.645 132.936,147.915 133.469,147.915 133.479,147.905
  Bottom Layer w0.254: 131.88,148.26 132.312,148.26 132.666,147.906 132.666,147.645
  other v1: 179.475,93.72 181.56,93.72 183.645,93.72 129.29,94.062 131.387,94.062 133.484,94.062 135.581,94.062 137.678,94.062 139.775,94.062 141.872,94.062 143.969,94.062 146.066,94.062 148.163,94.062 150.26,94.062 152.357,94.062 187.941,95.109 187.941,97.194 187.941,99.279 142.439,100.574 187.941,101.363 187.941,103.448 187.941,105.533 131.138,105.655 187.941,107.617 146.886,108.322 146.378,108.83 187.941,109.702 148.535,110.226 148.027,110.734 147.456,111.135 133.807,111.479 187.941,111.787 187.941,113.872 187.941,115.956 187.941,118.041 187.941,120.126 187.941,122.21 187.941,124.295 187.941,126.38 187.941,128.464 187.941,130.549 122.796,131.715 187.941,132.634 187.941,134.718 187.941,136.803 187.941,138.888 187.941,140.972 131.004,141.249 140.223,156.047 142.32,156.047 117.754,156.107 119.851,156.107 121.948,156.107 124.045,156.107 126.142,156.107
  other v2: 145.132,115.678 145.219,116.82 170.436,118.815 145.66,120.9 163.519,120.96 162.859,121.56 162.379,122.4

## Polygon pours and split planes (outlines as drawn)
no net on Top Layer (solid, remove dead copper, pour order 34): 78.48,84.12 196.74,84.12 196.74,162.6 78.48,162.6
no net on Bottom Layer (solid, remove dead copper, pour order 78): 76.2,76.2 195.96,76.2 195.96,166.14 76.2,166.14
OUT_BATT1 on Bottom Layer (solid, remove dead copper, pour order 36): 174,140.496 174,144.137 175.8,146.073 175.8,150.65 180.12,150.65 180.12,137.47 179,136.35 176.427,136.35 176.427,139.869 175.8,140.496
SW on Top Layer (solid, remove dead copper): 133.883,141.729 134.793,141.736 135.276,142.219 136.165,142.219 137.473,143.527 137.473,150.279 136.636,151.239 133.577,151.239 133.34,150.952 133.411,143.112
$1N27791 on Bottom Layer (solid, remove dead copper, pour order 38): 152.116,133.078 152.3,133.078 152.3,133.1 152.2,133.2 152.2,133.162
OUT_BATT on Top Layer (solid, remove dead copper, pour order 2): 159.312,152.5 159.312,127.845 143.823,127.5 132.3,127.5 130.581,129.219 130.581,133.11 130.844,133.373 131.822,133.373 133.279,134.272 133.279,135.063 133.422,135.245 134.052,135.243 134.127,135.157 134.127,131.804 132.962,131.09 132.967,130.45 133.495,130.107 150.775,130.098 153.905,133.883 153.905,152.5
+5V on Top Layer (solid, remove dead copper, pour order 4): 139.707,120.112 143.328,119.878 143.487,116.262 144.205,114.583 144.205,109.039 143.988,108.727 143.988,108.053 143.781,107.846 143.013,107.846 142.807,108.052 142.807,110.83 139.707,113.93
$1N27791 on Bottom Layer (solid, remove dead copper, pour order 40): 152.3,131.1 157.8,131.1 158.2,130.7 158.2,123.4 158.1,123.3 152.2,123.3 152.1,123.2 152.1,130.9
SW_1 on Top Layer (solid, remove dead copper, pour order 6): 129.441,122.627 134.856,122.627 135.729,121.754 135.729,117.516 135.183,116.828 129.323,116.828 127.87,118.28 127.87,121.055
$1N2164 on Bottom Layer (solid, remove dead copper, pour order 42): 172,133.26 178.34,133.26 178.34,120.243 172,120.24
VOUT1 on Top Layer (solid, remove dead copper, pour order 8): 140.846,106.164 142.167,106.164 142.566,106.797 142.88,107.165 145.543,107.165 145.717,106.992 145.717,105.005 145.391,104.679 142.748,104.679 142.267,105.179 140.907,105.179 140.807,105.279 140.807,106.125
OUT_BATT2 on Bottom Layer (solid, remove dead copper, pour order 44): 158,149.7 158.673,149.7 158,150.373
$2N28 on Top Layer (solid, remove dead copper, pour order 10): 168.97,151.305 173.493,151.305 173.561,144.281 172.68,143.4 169.538,143.4 168.97,144.479
OUT_BATT2 on Bottom Layer (solid, remove dead copper, pour order 46): 162.438,150.716 166.671,150.716 166.671,145.367 162.861,140.052 162.861,136.181 161.421,136.205 160.063,135.624 156.912,135.587 156.5,136 156.5,139.56 162.438,146.6
UBATT on Bottom Layer (solid, remove dead copper, pour order 48): 152.081,116.501 152.081,114.152 155.85,110.051 171.751,110.051 173.873,112.173 173.873,117.5 172,117.5 171.362,116.862 171.362,113.181 169.981,111.8 157.3,111.8 154.254,114.846 154.254,116.023 153.58,116.501
OUT_BATT on Top Layer (solid, remove dead copper, pour order 12): 159.351,104.98 159.351,129.135 153.525,129.08 156.384,125.592 156.484,104.907 157.341,104.049 158.42,104.049
OUT_BATT on Bottom Layer (solid, remove dead copper, pour order 50): 157.019,104.619 157.411,104.227 163.211,104.227 163.908,104.614 163.908,105.214 162.919,106.203 157.541,106.203 157.019,105.783
+5V on Top Layer (solid, remove dead copper, pour order 14): 122.5,124.316 122.5,126.378 123.262,126.736 141.766,126.736 143.499,125.003 143.499,120.558 142.185,119.243 140.153,119.243 139.645,119.751 139.645,122.926 138.756,123.815 123.272,123.815
+5V on Bottom Layer (solid, remove dead copper, pour order 52): 118.621,151.574 121.677,151.574 122.046,151.115 122.046,127.571 122.881,126.736 125.322,126.736 125.675,126.475 125.675,123.984 125.236,123.799 121.118,123.799 118.182,126.736 118.182,151.066
+5V on Top Layer (solid, remove dead copper, pour order 16): 96.895,151.274 97.26,151.628 121.94,151.628 122.487,151.081 122.487,149.329 121.865,148.707 118.158,148.707 116.761,150.104 97.098,150.104 96.895,150.41
+5V on Top Layer (solid, remove dead copper, pour order 18): 121.23,126.736 126.31,126.736 126.945,126.101 126.945,124.577 125.281,122.913 125.281,102.929 124.808,102.356 122.626,102.356 121.738,102.851 121.738,122.914 120.595,124.45
VOUT1 on Bottom Layer (solid, remove dead copper, pour order 54): 147.392,103.163 147.1,102.86 134.946,102.86 118.276,119.53 97.064,119.53 96.752,119.667 96.752,120.74 98.322,121.188 119.539,121.188 135.835,104.892 147.138,104.892 147.392,104.638
+5V on Top Layer (solid, remove dead copper, pour order 20): 96.755,113.276 97.328,113.653 121.103,113.653 122.5,115.05 122.5,110.732 122.373,110.605 121.103,111.875 97.379,111.875 96.755,112.224
+5V on Bottom Layer (solid, remove dead copper, pour order 56): 123.319,104.16 124.639,104.16 125.119,103.68 125.119,100.435 122.993,98.308 119.151,98.308 119.151,100.108 121.846,104.178 123.302,104.178
no net on Bottom Layer (solid, remove dead copper, pour order 58): 148.989,133.331 148.289,133.331 cw(c148.289,133.434) 148.187,133.434 148.187,134.334 cw(c148.289,134.334) 148.289,134.436 148.989,134.436 cw(c148.989,134.334) 149.092,134.334 149.092,133.434 cw(c148.989,133.434)
+5V on Top Layer (solid, remove dead copper, pour order 22): 118.116,151.215 119.256,152.355 126.456,152.355 127.296,151.515 127.296,146.414 118.574,146.414 118.116,146.882
no net on Bottom Layer (solid, remove dead copper, pour order 60): 148.989,133.331 148.289,133.331 cw(c148.289,133.434) 148.187,133.434 148.187,134.334 cw(c148.289,134.334) 148.289,134.436 148.989,134.436 cw(c148.989,134.334) 149.092,134.334 149.092,133.434 cw(c148.989,133.434)
+5V on Top Layer (solid, remove dead copper, pour order 24): 128.366,137.758 128.571,137.554 128.571,137.01 128.376,136.815 122.022,136.806 121.498,136.428 121.498,137.902 121.747,137.758
no net on Bottom Layer (solid, remove dead copper, pour order 62): 148.989,133.331 148.289,133.331 cw(c148.289,133.434) 148.187,133.434 148.187,134.334 cw(c148.289,134.334) 148.289,134.436 148.989,134.436 cw(c148.989,134.334) 149.092,134.334 149.092,133.434 cw(c148.989,133.434)
+5V on Top Layer (solid, remove dead copper, pour order 26): 96.861,144.128 114.042,144.087 115.644,142.485 115.644,139.564 116.914,138.294 121.105,138.294 121.613,137.786 121.613,136.135 121.232,135.754 116.406,135.754 113.358,138.802 113.358,141.588 112.641,142.517 97.415,142.517 96.76,142.98
no net on Bottom Layer (solid, remove dead copper, pour order 64): 148.187,133.434 148.187,134.334 cw(c148.289,134.334) 148.289,134.436 148.989,134.436 cw(c148.989,134.334) 149.092,134.334 149.092,133.434 cw(c148.989,133.434) 148.989,133.331 148.289,133.331 cw(c148.289,133.434)
+5V on Top Layer (solid, remove dead copper, pour order 28): 110.928,136.312 113.799,139.183 115.323,139.183 116.974,137.532 116.974,136.262 115.223,134.795 97.086,134.795 97.086,136.312
EN3V3 on Bottom Layer (solid, remove dead copper, pour order 66): 122.939,133.875 124.119,135.055 126.129,135.055 126.129,134.231 126.281,134.08 126.281,133.25 125.786,132.755 125.786,131.999 123.901,131.999 122.939,132.961
ADC1 on Top Layer (solid, remove dead copper, pour order 30): 96.88,128.58 107.56,128.58 107.98,128.16 107.98,127.62 107.68,127.32 97.18,127.32 96.88,127.62
+5V on Bottom Layer (solid, remove dead copper, pour order 68): 121.656,127.935 122.373,128.652 125.777,128.636 125.916,128.775 125.916,129.522 125.604,129.834 122.277,129.834 121.656,130.455
$2N30 on Top Layer (solid, remove dead copper, pour order 32): 182.513,151.359 186.613,151.359 186.613,144.309 185.738,143.435 183.507,143.435 182.513,144.43
+3V3 on Bottom Layer (solid, remove dead copper, pour order 70): 127.795,129.635 128.1,129.33 128.1,127.967 127.695,127.562 126.877,127.562 126.347,128.093 126.347,129.354 126.628,129.635
ISHUNT on Bottom Layer (solid, remove dead copper, pour order 72): 97.338,125.04 106.805,125.039 107.115,124.663 107.121,123.531 106.396,123.343 97.489,123.291 97,123.78 97,124.74
+5V on Bottom Layer (solid, remove dead copper, pour order 74): 96.76,105.48 97.3,106.02 112.455,106.02 117.751,100.552 121.912,99.452 121.912,98.46 117.559,98.46 111.685,104.4 97.18,104.4 96.88,104.7 96.88,105.36
no net on Bottom Layer (solid, remove dead copper, pour order 76): 130.127,145.916 130.311,146.1 131.28,146.1 131.34,146.04 131.166,145.866 131.166,144.886 130.8,144.52 130.8,144.48 130.76,144.52 130.318,144.52 130.318,145.682 130.2,145.8 130.2,145.844

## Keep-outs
Bottom Layer:
  region: 125.856,130.035 127.836,130.035 127.836,129.915 127.776,129.855 126.096,129.855 126.036,129.915 125.976,129.915
Board Outline Layer:
  lines w0.254: 95.1,92.7 189.1,92.7 189.1,157.88 95.1,157.88 95.1,92.7
Multi-Layer:
  circle w0.254: c113.495,138.083 r1.25
  circle w0.254: c113.512,115.196 r1.25
  circle w0.254: c113.495,138.083 r1.552
  region: 131.72,136.6 136.02,136.6 136.02,141.649 131.72,141.649
  region: 137.894,106.354 141.756,106.354 141.756,110.685 137.894,110.685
